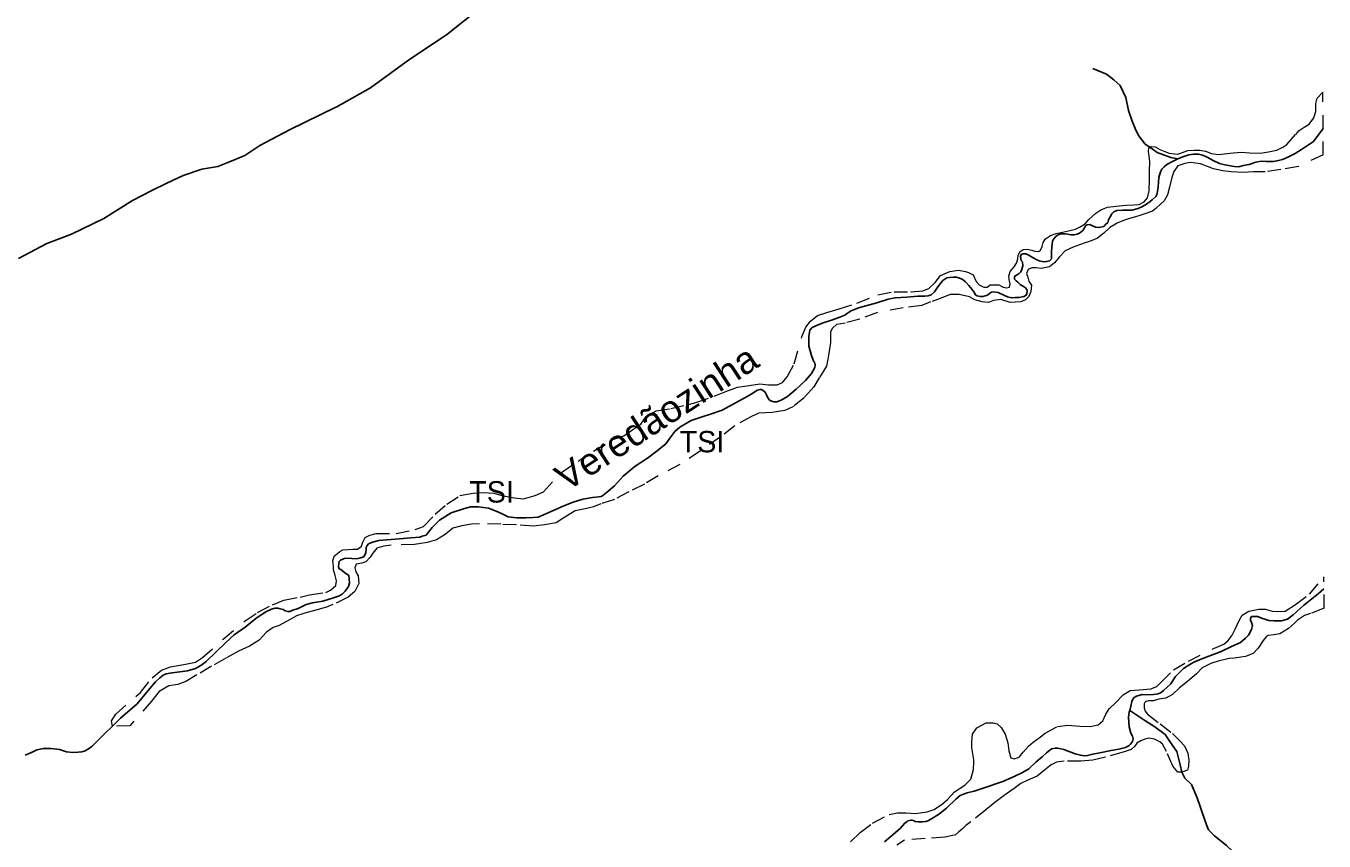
# Model space of a CAD drawing. Extents: x 391.8 to 446, y 8452 to 8507.5.
# Drawn here: x 436.28 to 445.97, y 8466.06 to 8472.15 of the extents above; entities that cross this region are included whole.
import ezdxf
from ezdxf.enums import TextEntityAlignment as Align

# ---------------------------------------------------------------- set-up
doc = ezdxf.new("R2010")
doc.units = 0
doc.header["$LTSCALE"] = 0.064
doc.linetypes.add('LONG_DASHED', pattern=[7.5, 6, -1.5])
doc.linetypes.add('SHORT_DASHED', pattern=[2.7, 1.5, -1.2])
for name, color, linetype, lineweight in [('21', 7, 'SHORT_DASHED', 13), ('62', 7, 'SHORT_DASHED', 13), ('7', 7, 'Continuous', 25), ('9', 7, 'LONG_DASHED', 25)]:
    doc.layers.add(name, color=color, linetype=linetype, lineweight=lineweight)
doc.layers.add('61', color=7, linetype='Continuous')

msp = doc.modelspace()

# ---------------------------------------------------------------- linework, layer by layer
at = {"layer": '21'}
for points in [[(444.6682, 8471.2438), (444.6796, 8471.2503), (444.708, 8471.2477), (444.7442, 8471.2271), (444.7803, 8471.2116), (444.8138, 8471.2013), (444.8758, 8471.1936), (444.9119, 8471.2039), (444.9532, 8471.2193), (444.9997, 8471.2219), (445.041, 8471.2219), (445.0849, 8471.2142), (445.1287, 8471.1987), (445.1803, 8471.191), (445.2465, 8471.1989), (445.2918, 8471.2027), (445.3548, 8471.2078), (445.4116, 8471.2026), (445.4941, 8471.2), (445.5535, 8471.2104), (445.6155, 8471.2232), (445.6619, 8471.2439), (445.6903, 8471.2645), (445.7574, 8471.3392), (445.7832, 8471.3702), (445.8219, 8471.3934), (445.8581, 8471.4166), (445.8916, 8471.463), (445.9071, 8471.5119), (445.9071, 8471.5712), (445.9174, 8471.6099), (445.9609, 8471.6559)], [(443.067, 8470.2353), (443.1075, 8470.2872), (443.1768, 8470.3161), (443.2404, 8470.3276), (443.2924, 8470.3161), (443.3155, 8470.3103), (443.3501, 8470.293), (443.3733, 8470.2411), (443.3964, 8470.218), (443.431, 8470.2007), (443.4541, 8470.2007), (443.4773, 8470.218), (443.5408, 8470.218), (443.5755, 8470.2007), (443.5986, 8470.1949), (443.6217, 8470.2007), (443.6275, 8470.2237), (443.6217, 8470.2411), (443.6159, 8470.2814), (443.6275, 8470.3161), (443.6564, 8470.3507), (443.6737, 8470.3795), (443.6848, 8470.4111), (443.6874, 8470.4395), (443.7003, 8470.4653), (443.7235, 8470.4807), (443.7545, 8470.4833), (443.788, 8470.4756), (443.8113, 8470.4678), (443.8371, 8470.4653), (443.8526, 8470.4756), (443.8655, 8470.5039), (443.8732, 8470.5323), (443.8913, 8470.5606), (443.9274, 8470.5864), (443.9687, 8470.5993), (444.0177, 8470.6096), (444.0616, 8470.6199), (444.1132, 8470.6328), (444.1442, 8470.6483), (444.1855, 8470.6715), (444.2139, 8470.705), (444.2655, 8470.7514), (444.3042, 8470.7771), (444.3533, 8470.7978), (444.3971, 8470.8029), (444.4436, 8470.8081), (444.4926, 8470.8107), (444.5494, 8470.8132), (444.5881, 8470.8158), (444.6269, 8470.8364), (444.6527, 8470.8674), (444.663, 8470.9189), (444.6667, 8471.0054), (444.6667, 8471.0673), (444.6693, 8471.1343), (444.6641, 8471.1807), (444.659, 8471.209), (444.6616, 8471.24), (444.6682, 8471.2438)], [(445.9619, 8471.1876), (445.7778, 8471.1011), (445.646, 8471.0785)], [(445.646, 8471.0785), (445.5291, 8471.0597), (445.4425, 8471.0597), (445.3634, 8471.0559), (445.2767, 8471.0597), (445.2126, 8471.0672), (445.1448, 8471.0823), (445.0996, 8471.1011), (445.0468, 8471.1199), (444.9715, 8471.1312), (444.93, 8471.1237), (444.8773, 8471.1048), (444.8471, 8471.0635), (444.8321, 8471.0183), (444.8161, 8470.9452), (444.801, 8470.8887), (444.7747, 8470.8435), (444.7521, 8470.821), (444.7144, 8470.7871), (444.688, 8470.7683), (444.6239, 8470.7457), (444.5787, 8470.7307), (444.5184, 8470.7118), (444.4732, 8470.6968), (444.4242, 8470.678), (444.3715, 8470.6441), (444.3263, 8470.6027), (444.2773, 8470.5651), (444.2321, 8470.5463), (444.1793, 8470.5274), (444.0964, 8470.4973), (444.0361, 8470.471), (443.9947, 8470.4258), (443.957, 8470.3807), (443.9193, 8470.3506), (443.859, 8470.3393), (443.8213, 8470.343), (443.7874, 8470.343), (443.761, 8470.3318), (443.7497, 8470.3017), (443.7573, 8470.2753), (443.7648, 8470.2452), (443.7857, 8470.2136), (443.782, 8470.1684), (443.7669, 8470.1308), (443.7405, 8470.1045), (443.7066, 8470.0894), (443.6275, 8470.0856), (443.5559, 8470.1082), (443.5031, 8470.1007), (443.4654, 8470.0856), (443.4164, 8470.0894), (443.3637, 8470.1045), (443.3222, 8470.127), (443.2469, 8470.1459), (443.1791, 8470.1459), (443.1376, 8470.127), (443.0321, 8470.0894), (442.968, 8470.0631), (442.8286, 8470.0443), (442.6365, 8470.0104), (442.5046, 8469.9615), (442.3953, 8469.9314), (442.3312, 8469.9201), (442.3011, 8469.8937), (442.2849, 8469.866), (442.2849, 8469.7869), (442.2698, 8469.6891), (442.2547, 8469.6101), (442.202, 8469.5235), (442.1605, 8469.4558), (442.0927, 8469.3768), (442.0098, 8469.309), (441.9457, 8469.2789), (441.8515, 8469.2639), (441.7498, 8469.2601), (441.697, 8469.2338), (441.5712, 8469.1648), (441.4656, 8469.082), (441.3149, 8468.9767), (441.1604, 8468.8751), (440.9984, 8468.7923), (440.8967, 8468.7283), (440.7799, 8468.6718), (440.6743, 8468.6154), (440.5726, 8468.5815), (440.5161, 8468.5589), (440.4671, 8468.5477), (440.3804, 8468.5288), (440.3032, 8468.482), (440.2392, 8468.4406), (440.1525, 8468.4256), (440.0696, 8468.4143), (439.9415, 8468.4256), (439.8247, 8468.4293)], [(436.9267, 8466.9228), (436.9206, 8466.9626), (436.9523, 8467.0123), (437.1358, 8467.174), (437.2225, 8467.2836), (437.2918, 8467.3413), (437.3611, 8467.3644), (437.4594, 8467.3817), (437.546, 8467.399), (437.598, 8467.4336), (437.754, 8467.5721), (437.9181, 8467.7073), (438.0105, 8467.7708), (438.1203, 8467.8285), (438.207, 8467.8631), (438.3283, 8467.8862), (438.3977, 8467.9035), (438.519, 8467.9209), (438.5537, 8467.9382), (438.5941, 8467.9728), (438.5999, 8468.0074), (438.5883, 8468.0478), (438.5768, 8468.0882), (438.5768, 8468.117), (438.571, 8468.1574), (438.5826, 8468.1921), (438.623, 8468.2267), (438.6461, 8468.2382), (438.7212, 8468.244), (438.7559, 8468.244), (438.7848, 8468.2671), (438.7963, 8468.2959), (438.8137, 8468.3306), (438.8483, 8468.3479), (438.8946, 8468.3594), (439.0448, 8468.3594), (439.185, 8468.3897), (439.2486, 8468.4128), (439.3353, 8468.5051), (439.4219, 8468.5801), (439.5202, 8468.6436), (439.6184, 8468.6609), (439.6935, 8468.6667), (439.7744, 8468.6609), (439.8322, 8468.6436), (439.9246, 8468.6263), (439.994, 8468.6205), (440.0806, 8468.6436), (440.1442, 8468.6725), (440.2713, 8468.811), (440.4016, 8468.9002), (440.5171, 8468.9753), (440.6616, 8469.0618), (440.7425, 8469.0907), (440.8176, 8469.1426), (440.8696, 8469.1772), (440.91, 8469.2349), (440.9851, 8469.2753), (441.0949, 8469.2926), (441.2162, 8469.3215), (441.2798, 8469.3388), (441.4185, 8469.385), (441.5051, 8469.4196), (441.5918, 8469.4542), (441.6785, 8469.4657), (441.7594, 8469.4773), (441.8229, 8469.4715), (441.8865, 8469.4715), (441.9269, 8469.4888), (441.9616, 8469.5292), (442.0136, 8469.6273), (442.0714, 8469.8293), (442.1021, 8469.9006), (442.1368, 8469.9468), (442.1888, 8469.9872), (442.2581, 8470.0102), (442.3505, 8470.0391), (442.4834, 8470.0795), (442.6394, 8470.143), (442.7608, 8470.166), (442.8821, 8470.166), (442.9746, 8470.1718), (443.0208, 8470.1891), (443.067, 8470.2353)], [(439.8247, 8468.4293), (439.6664, 8468.4331), (439.6062, 8468.4293), (439.5346, 8468.418), (439.4667, 8468.3992), (439.4102, 8468.3541), (439.3462, 8468.3127)], [(439.3462, 8468.3127), (439.2746, 8468.2938), (439.1804, 8468.2788), (439.0059, 8468.2735), (438.9531, 8468.266), (438.9004, 8468.2509), (438.8702, 8468.2133), (438.8514, 8468.1832), (438.8175, 8468.1493), (438.7873, 8468.138), (438.7459, 8468.1305), (438.7346, 8468.1042), (438.7421, 8468.0741), (438.761, 8468.044), (438.7647, 8467.9875), (438.7346, 8467.9273), (438.6856, 8467.8859), (438.5726, 8467.8295), (438.5236, 8467.8106), (438.4444, 8467.7881), (438.3615, 8467.7655), (438.3012, 8467.7467), (438.2472, 8467.7152), (438.1718, 8467.6738), (438.1266, 8467.6587), (438.0776, 8467.6249), (438.0211, 8467.5646), (437.9495, 8467.5195), (437.8666, 8467.4819), (437.7724, 8467.4292), (437.6669, 8467.369), (437.5576, 8467.305), (437.4747, 8467.2561), (437.4145, 8467.2335), (437.3466, 8467.2222), (437.275, 8467.1808), (437.2185, 8467.1093), (437.0573, 8466.9237), (436.9267, 8466.9228)], [(445.5333, 8467.7962), (445.5816, 8467.7813), (445.6188, 8467.7776), (445.6782, 8467.7813), (445.7563, 8467.8296), (445.8604, 8467.9075), (445.9685, 8468.0379)], [(442.4359, 8466.0578), (442.5065, 8466.1284), (442.5994, 8466.1989), (442.7237, 8466.2636), (442.7869, 8466.2747), (442.8501, 8466.2747), (442.9207, 8466.271), (443.0062, 8466.2821), (443.0582, 8466.3007), (443.1214, 8466.3415), (443.1586, 8466.3749), (443.2106, 8466.4306), (443.2887, 8466.4826), (443.3333, 8466.5272), (443.3519, 8466.5977), (443.3556, 8466.6534), (443.3556, 8466.6719), (443.3407, 8466.761), (443.3407, 8466.8056), (443.3445, 8466.8613), (443.3779, 8466.9095), (443.4485, 8466.9467), (443.5006, 8466.9467), (443.5303, 8466.9392), (443.5601, 8466.9132), (443.5898, 8466.8613), (443.6084, 8466.7982), (443.6158, 8466.7388), (443.6307, 8466.6868), (443.6567, 8466.6794), (443.6939, 8466.6905), (443.7236, 8466.7276), (443.7645, 8466.7722), (443.798, 8466.8019), (443.8537, 8466.8427), (443.8872, 8466.8687), (443.9787, 8466.9184), (444.0567, 8466.9296), (444.146, 8466.9221), (444.224, 8466.9184), (444.2835, 8466.9333), (444.317, 8466.963), (444.3393, 8467.0112), (444.3653, 8467.0521), (444.4136, 8467.0966), (444.4694, 8467.156), (444.5214, 8467.1894), (444.6218, 8467.1968), (444.6775, 8467.2006), (444.7221, 8467.2191), (444.7519, 8467.2488), (444.8448, 8467.3416), (444.9563, 8467.4084), (445.1347, 8467.4975), (445.2202, 8467.5347), (445.2537, 8467.5607), (445.2834, 8467.6015), (445.3057, 8467.646), (445.3362, 8467.7108), (445.3585, 8467.7516), (445.4069, 8467.7813), (445.4812, 8467.7962), (445.5333, 8467.7962)], [(445.969, 8467.8042), (445.8683, 8467.7626), (445.8237, 8467.7477), (445.7717, 8467.7143), (445.7494, 8467.6921), (445.7048, 8467.6512), (445.6379, 8467.6104), (445.5933, 8467.603), (445.5524, 8467.5992), (445.5375, 8467.5881), (445.5152, 8467.5621), (445.477, 8467.505), (445.4398, 8467.4641), (445.384, 8467.4418), (445.2985, 8467.4307), (445.2614, 8467.427), (445.1796, 8467.4084), (445.1238, 8467.3899), (445.0606, 8467.3565), (445.016, 8467.3119), (444.9491, 8467.2562), (444.8896, 8467.208), (444.8376, 8467.1597), (444.7893, 8467.13), (444.7372, 8467.1226), (444.6963, 8467.1114), (444.6592, 8467.1114), (444.6331, 8467.104), (444.6257, 8467.0892), (444.6257, 8467.0595), (444.6331, 8467.0335), (444.6517, 8467.0112), (444.7451, 8466.9389), (444.838, 8466.8683), (444.8938, 8466.8127), (444.9272, 8466.7755), (444.9532, 8466.7199), (444.9607, 8466.6679), (444.957, 8466.6233), (444.9495, 8466.5936), (444.9163, 8466.5804)], [(444.907, 8466.5788), (444.8789, 8466.5788), (444.8408, 8466.6244), (444.7924, 8466.7321), (444.7627, 8466.7878), (444.7441, 8466.8063), (444.7032, 8466.8249), (444.6623, 8466.8323), (444.6326, 8466.8249), (444.6028, 8466.8137), (444.5731, 8466.7952), (444.5582, 8466.7729), (444.5285, 8466.7469), (444.469, 8466.7284), (444.3389, 8466.6912), (444.2444, 8466.6678), (444.1552, 8466.6604), (444.0288, 8466.6604), (443.973, 8466.653), (443.9321, 8466.6344), (443.8838, 8466.5936), (443.8281, 8466.549), (443.7574, 8466.5193), (443.7054, 8466.4933), (443.6571, 8466.4562), (443.5827, 8466.4042), (443.5121, 8466.3523), (443.4452, 8466.2966), (443.3337, 8466.2075), (443.2965, 8466.1815), (443.2742, 8466.1592), (443.2407, 8466.1295), (443.2184, 8466.111), (443.1403, 8466.0938), (442.9916, 8466.0826), (442.8392, 8466.0715), (442.7798, 8466.0344)], [(444.9163, 8466.5804), (444.9124, 8466.5788), (444.907, 8466.5788)]]:
    msp.add_lwpolyline(points, dxfattribs=at)
at = {"layer": '62'}
for points in [[(445.9619, 8471.1876), (445.9615, 8471.3841), (445.9609, 8471.6559)], [(445.969, 8467.8042), (445.9686, 8467.9985), (445.9685, 8468.0379)]]:
    msp.add_lwpolyline(points, dxfattribs=at)
at = {"layer": '7'}
for points in [[(444.8786, 8471.1574), (444.9232, 8471.1755), (444.9601, 8471.1873), (444.9941, 8471.1918), (445.0325, 8471.1918), (445.062, 8471.1844), (445.0975, 8471.1696), (445.1418, 8471.146), (445.1876, 8471.1239), (445.2275, 8471.1136), (445.2984, 8471.1018), (445.3314, 8471.0989), (445.3669, 8471.1078), (445.4097, 8471.1166), (445.4599, 8471.1329), (445.5028, 8471.1402), (445.5382, 8471.1388), (445.5914, 8471.1388), (445.6283, 8471.1447), (445.6578, 8471.152), (445.6948, 8471.1683), (445.7529, 8471.1965), (445.8002, 8471.2275), (445.8902, 8471.288), (445.9615, 8471.3841)], [(444.2216, 8470.6678), (444.2357, 8470.6589), (444.2642, 8470.6471), (444.2906, 8470.6442), (444.3125, 8470.6495), (444.3256, 8470.6532), (444.3361, 8470.666), (444.356, 8470.6837), (444.3612, 8470.7035), (444.3737, 8470.726), (444.386, 8470.7474), (444.3992, 8470.7624), (444.4217, 8470.7717), (444.4649, 8470.7736), (444.5344, 8470.7755), (444.5814, 8470.7868), (444.6152, 8470.8018), (444.6452, 8470.8186), (444.6715, 8470.8393), (444.6866, 8470.8524), (444.7129, 8470.8768), (444.7204, 8470.8918), (444.726, 8470.9143), (444.7316, 8470.95), (444.7373, 8471.0194), (444.749, 8471.0616), (444.7584, 8471.0804), (444.7753, 8471.0972), (444.7959, 8471.116), (444.8335, 8471.1366), (444.8786, 8471.1574)], [(442.1436, 8469.6902), (442.123, 8469.7596), (442.123, 8469.8346), (442.1305, 8469.8796), (442.1493, 8469.8984), (442.1774, 8469.9115), (442.23, 8469.9322), (442.2939, 8469.9528), (442.3559, 8469.9753), (442.392, 8469.9913), (442.4127, 8470.0063), (442.439, 8470.0232), (442.4935, 8470.0457), (442.6306, 8470.0833), (442.7151, 8470.1095), (442.7677, 8470.1208), (442.856, 8470.1245), (442.9386, 8470.132), (442.9894, 8470.132), (443.0138, 8470.1358), (443.0363, 8470.1433), (443.0607, 8470.1658), (443.087, 8470.2014), (443.1246, 8470.2502), (443.1538, 8470.2696), (443.1726, 8470.2715), (443.2027, 8470.2752), (443.2271, 8470.2752), (443.2477, 8470.2659), (443.2684, 8470.2584), (443.2928, 8470.2396), (443.3191, 8470.2133), (443.3417, 8470.1852), (443.3548, 8470.1646), (443.3679, 8470.1421), (443.3792, 8470.1345), (443.4018, 8470.1308), (443.4224, 8470.1289), (443.4412, 8470.1345), (443.4581, 8470.1402), (443.4731, 8470.1533), (443.4882, 8470.1627), (443.4994, 8470.1646), (443.537, 8470.1589), (443.5783, 8470.1402), (443.6065, 8470.127), (443.6384, 8470.1195), (443.6647, 8470.1214), (443.6948, 8470.1233), (443.7286, 8470.1289), (443.7455, 8470.1402), (443.7511, 8470.1533), (443.753, 8470.1702), (443.7511, 8470.1814), (443.7399, 8470.1946), (443.7267, 8470.2058), (443.7023, 8470.2208), (443.6835, 8470.2358), (443.6704, 8470.2471), (443.6591, 8470.2584), (443.658, 8470.2758), (443.6637, 8470.2852), (443.6787, 8470.2927), (443.6937, 8470.302), (443.705, 8470.3133), (443.7144, 8470.3321), (443.72, 8470.3583), (443.7182, 8470.3883), (443.7088, 8470.3996), (443.705, 8470.4108), (443.7031, 8470.4296), (443.7088, 8470.4427), (443.7238, 8470.4484), (443.7445, 8470.4484), (443.7614, 8470.4409), (443.7864, 8470.4259), (443.8202, 8470.4072), (443.8433, 8470.3959), (443.8759, 8470.3883), (443.8985, 8470.3902), (443.921, 8470.3958), (443.9342, 8470.4108), (443.936, 8470.4371), (443.936, 8470.4671), (443.9379, 8470.5009), (443.9417, 8470.5422), (443.9511, 8470.559), (443.968, 8470.5778), (443.9792, 8470.5872), (444.0037, 8470.5984), (444.0375, 8470.5984), (444.0563, 8470.5966), (444.0788, 8470.5909), (444.1051, 8470.5909), (444.1258, 8470.5947)], [(444.1258, 8470.5947), (444.1445, 8470.6041), (444.169, 8470.6228), (444.1821, 8470.6435), (444.1878, 8470.6566), (444.2009, 8470.666), (444.2216, 8470.6678)], [(442.1002, 8469.5035), (442.1434, 8469.5541), (442.168, 8469.6001), (442.1718, 8469.6208), (442.168, 8469.6339), (442.1624, 8469.6433), (442.1436, 8469.6902)], [(438.3124, 8467.8017), (438.3725, 8467.8298), (438.4195, 8467.843), (438.4965, 8467.8561), (438.5754, 8467.8805), (438.6205, 8467.8955), (438.6449, 8467.9105), (438.6637, 8467.9292), (438.6881, 8467.9649), (438.6956, 8467.9912), (438.6937, 8468.023), (438.69, 8468.0474), (438.6599, 8468.0699), (438.6318, 8468.0906), (438.6187, 8468.0974), (438.6149, 8468.1124), (438.6168, 8468.1368), (438.6187, 8468.1518), (438.6281, 8468.1612), (438.6638, 8468.1762), (438.7145, 8468.1743), (438.7464, 8468.1724), (438.7802, 8468.178), (438.8009, 8468.1874), (438.8103, 8468.1987), (438.8178, 8468.2193), (438.8197, 8468.2437), (438.8197, 8468.2568), (438.8272, 8468.2718), (438.8385, 8468.2831), (438.8666, 8468.2962), (438.9155, 8468.3075), (439.0667, 8468.3208), (439.155, 8468.3283), (439.2207, 8468.332), (439.2395, 8468.3414), (439.2677, 8468.3489), (439.2865, 8468.3714), (439.3128, 8468.4052), (439.3673, 8468.4596), (439.4555, 8468.514), (439.5551, 8468.5477), (439.6021, 8468.5609), (439.6302, 8468.559), (439.6584, 8468.559), (439.7335, 8468.5496), (439.803, 8468.5234), (439.8406, 8468.5046), (439.8801, 8468.4858), (439.9458, 8468.4765), (440.0111, 8468.4771), (440.0675, 8468.479), (440.1032, 8468.4827), (440.1614, 8468.5071), (440.2966, 8468.5672), (440.3642, 8468.5934), (440.4375, 8468.6178), (440.5089, 8468.6291), (440.5567, 8468.6334), (440.5736, 8468.6371), (440.5867, 8468.6446), (440.6112, 8468.6634), (440.6731, 8468.7159), (440.7389, 8468.7891), (440.8272, 8468.8641), (440.9192, 8468.9223), (440.9925, 8468.9767), (441.0563, 8469.0292), (441.0944, 8469.0829), (441.1245, 8469.1223), (441.1602, 8469.1542), (441.2447, 8469.203), (441.3349, 8469.2349), (441.3912, 8469.2517), (441.4776, 8469.2818), (441.5828, 8469.338), (441.6644, 8469.3834), (441.7057, 8469.4078), (441.7245, 8469.421), (441.7414, 8469.4303), (441.7602, 8469.436), (441.7696, 8469.436), (441.779, 8469.4303), (441.7902, 8469.4228), (441.7996, 8469.4097), (441.809, 8469.3947), (441.8165, 8469.3778), (441.8278, 8469.359), (441.841, 8469.3515), (441.8616, 8469.344), (441.8842, 8469.344), (441.918, 8469.3572), (441.9649, 8469.3834), (442.0288, 8469.4378), (442.1002, 8469.5035)], [(444.5185, 8467.0398), (444.5268, 8467.0708), (444.5345, 8467.1067), (444.5421, 8467.1233), (444.5524, 8467.1361), (444.5691, 8467.1463), (444.6126, 8467.1579), (444.6536, 8467.1566), (444.6972, 8467.1591), (444.7305, 8467.1643), (444.7523, 8467.1732), (444.7703, 8467.1873), (444.8246, 8467.2391), (444.8579, 8467.2903), (444.8848, 8467.3185), (444.9194, 8467.3518), (444.9476, 8467.371), (444.9925, 8467.3978), (445.0565, 8467.4247), (445.2006, 8467.4795), (445.2775, 8467.5166), (445.3454, 8467.5473), (445.3826, 8467.5793), (445.4044, 8467.6024), (445.4287, 8467.6435), (445.4349, 8467.6741), (445.4287, 8467.6955), (445.4195, 8467.7138), (445.4195, 8467.7291), (445.4287, 8467.7414), (445.4747, 8467.7414), (445.5022, 8467.7291), (445.5267, 8467.72), (445.5574, 8467.7108), (445.5972, 8467.7077), (445.6523, 8467.7077), (445.6952, 8467.72), (445.7381, 8467.7536), (445.8147, 8467.824), (445.928, 8467.9127), (445.9687, 8467.9475)], [(436.9267, 8466.9228), (436.9881, 8466.9812), (437.1102, 8467.09), (437.1931, 8467.1884), (437.2475, 8467.254), (437.2813, 8467.2822), (437.3058, 8467.3028), (437.3283, 8467.314), (437.3715, 8467.3215), (437.4297, 8467.3272), (437.4861, 8467.3347), (437.5462, 8467.3534), (437.5856, 8467.3759), (437.6251, 8467.406), (437.7725, 8467.5459), (437.8344, 8467.6041), (437.9171, 8467.6604), (437.996, 8467.726), (438.0674, 8467.7729), (438.1143, 8467.7954), (438.1406, 8467.8029), (438.1613, 8467.8029), (438.1782, 8467.7992)], [(438.1782, 8467.7992), (438.2007, 8467.7936), (438.2158, 8467.7842), (438.2354, 8467.7773), (438.2523, 8467.7773), (438.2655, 8467.7848), (438.3124, 8467.8017)], [(442.6893, 8466.0586), (442.8046, 8466.1584), (442.8379, 8466.1955), (442.8572, 8466.2109), (442.8636, 8466.2147), (442.8751, 8466.2173), (442.8841, 8466.2198), (442.893, 8466.2198), (442.9097, 8466.2147), (442.9187, 8466.2096), (442.9405, 8466.2083), (442.9712, 8466.207), (442.9968, 8466.2096), (443.0122, 8466.216), (443.034, 8466.2288), (443.0917, 8466.2621), (443.1525, 8466.3088), (443.2204, 8466.3779), (443.2537, 8466.4035), (443.2781, 8466.4137), (443.305, 8466.424), (443.3575, 8466.4368), (443.4254, 8466.4598), (443.5728, 8466.5097), (443.6556, 8466.5475), (443.7196, 8466.577), (443.7658, 8466.6038), (443.817, 8466.6537), (443.8644, 8466.6921), (443.8978, 8466.7241), (443.9362, 8466.7523), (443.9631, 8466.7587), (443.9823, 8466.7574), (444.0272, 8466.7472), (444.1105, 8466.7165), (444.151, 8466.7052), (444.1805, 8466.7013), (444.2036, 8466.7026), (444.2433, 8466.7141), (444.2946, 8466.7231), (444.3791, 8466.741), (444.4381, 8466.7512), (444.4881, 8466.764), (444.515, 8466.7768), (444.5252, 8466.7884), (444.5406, 8466.8076), (444.5445, 8466.828), (444.5393, 8466.8472), (444.5265, 8466.8703), (444.514, 8466.9172), (444.5101, 8466.9889), (444.5152, 8467.0273), (444.5185, 8467.0398)], [(436.2751, 8466.7048), (436.3221, 8466.7254), (436.3634, 8466.7442), (436.4123, 8466.7554), (436.4686, 8466.7554), (436.5306, 8466.7479), (436.5832, 8466.731), (436.6302, 8466.7254), (436.6715, 8466.7273), (436.6978, 8466.731), (436.7241, 8466.7385), (436.756, 8466.7573), (436.7748, 8466.7723), (436.8698, 8466.8686), (436.9267, 8466.9228)]]:
    msp.add_lwpolyline(points, dxfattribs=at)
at = {"layer": '9'}
for points in [[(436.2248, 8470.413), (436.4378, 8470.5259), (436.6204, 8470.5953), (436.8638, 8470.7125), (437.0768, 8470.8471), (437.2203, 8470.9209), (437.3333, 8470.9774), (437.455, 8471.0338), (437.5941, 8471.0816), (437.7138, 8471.1012), (437.8007, 8471.1359), (437.9137, 8471.1837), (438.0268, 8471.2575), (438.2485, 8471.3747), (438.5962, 8471.544), (438.8527, 8471.6873), (439.1452, 8471.9015), (439.4191, 8472.0838), (439.6755, 8472.2879)], [(444.2444, 8471.8334), (444.3457, 8471.7908), (444.399, 8471.7482), (444.4469, 8471.7056), (444.4896, 8471.6151), (444.5109, 8471.5193), (444.5375, 8471.4395), (444.5601, 8471.3852), (444.5851, 8471.3311), (444.6348, 8471.2673), (444.6682, 8471.2438)], [(444.6682, 8471.2438), (444.7239, 8471.2046), (444.8253, 8471.168), (444.8786, 8471.1574)], [(444.5185, 8467.0398), (444.6307, 8466.9645), (444.7064, 8466.9183), (444.7821, 8466.8595), (444.8241, 8466.8008), (444.8704, 8466.7336), (444.8956, 8466.6328), (444.907, 8466.5788)], [(444.907, 8466.5788), (444.9293, 8466.535), (444.9796, 8466.4857), (445.0225, 8466.3879), (445.0736, 8466.2343), (445.0906, 8466.1864), (445.1056, 8466.149), (445.1522, 8466.1021), (445.2405, 8466.0307), (445.291, 8465.9845), (445.3108, 8465.9394), (445.3976, 8465.7081), (445.4355, 8465.6353)]]:
    msp.add_lwpolyline(points, dxfattribs=at)

# ---------------------------------------------------------------- texts
at = {"layer": '61', "width": 1.05}
msp.add_text('Veredãozinha', height=0.2, rotation=33.057, dxfattribs=at).set_placement((441.0414, 8469.1417), align=Align.CENTER)
at = {"layer": '61'}
for p in [(441.327, 8468.9663), (439.756, 8468.5915)]:
    msp.add_text('TSI', height=0.16, dxfattribs=at).set_placement(p, align=Align.CENTER)

doc.saveas('drawing.dxf')
